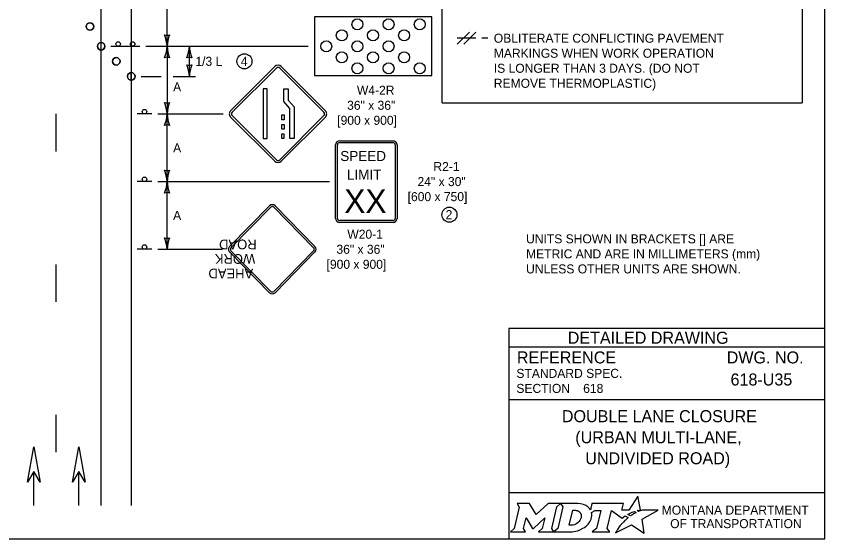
# Model space of a CAD drawing. Extents: x 49991.4 to 50021, y 49987.6 to 50011.4.
# Drawn here: x 50003.24 to 50008.61, y 50000.06 to 50003.54 of the extents above; entities that cross this region are included whole.
import ezdxf

# ---------------------------------------------------------------- set-up
doc = ezdxf.new("R2010")
doc.units = 0
for name, color, linetype in [('Level 1', 7, 'Continuous'), ('Level 2', 7, 'Continuous'), ('Level 3', 7, 'Continuous')]:
    doc.layers.add(name, color=color, linetype=linetype)

msp = doc.modelspace()

# ---------------------------------------------------------------- linework, layer by layer
at = {"layer": 'Level 1'}
for p, q in [((50004.006, 50011.0404), (50004.006, 50000.2848)), ((50003.806, 50000.2848), (50003.806, 50005.3678)), ((50006.1725, 50003.3523), (50006.2525, 50003.4323)), ((50006.2149, 50003.3523), (50006.2949, 50003.4323)), ((50006.2949, 50003.3923), (50006.1725, 50003.3923)), ((50003.8709, 50003.3385), (50003.9669, 50003.3385)), ((50003.9669, 50003.3385), (50004.0629, 50003.3385)), ((50004.6659, 50002.9095), (50004.9599, 50003.2036)), ((50004.9698, 50003.1936), (50004.6758, 50002.8996)), ((50004.9698, 50003.1936), (50004.9698, 50003.1936)), ((50005.286, 50002.8996), (50004.992, 50003.1936)), ((50005.0019, 50003.2036), (50005.2959, 50002.9095)), ((50004.9098, 50003.056), (50004.8823, 50003.056)), ((50004.8823, 50003.056), (50004.8823, 50002.7244)), ((50004.9098, 50002.7244), (50004.9098, 50003.056)), ((50005.0206, 50002.9703), (50005.0206, 50003.056)), ((50005.0206, 50003.056), (50005.0481, 50003.056)), ((50005.0481, 50003.056), (50005.0481, 50002.9805)), ((50005.0599, 50002.9246), (50005.0206, 50002.9703)), ((50005.0481, 50002.9805), (50005.0874, 50002.9348)), ((50003.5061, 50002.6382), (50003.5061, 50002.8882)), ((50004.142, 50002.8885), (50004.046, 50002.8885)), ((50005.0599, 50002.7244), (50005.0599, 50002.9246)), ((50005.0874, 50002.9348), (50005.0874, 50002.7244)), ((50004.9599, 50002.5735), (50004.6659, 50002.8675)), ((50004.6758, 50002.8774), (50004.9698, 50002.5834)), ((50004.992, 50002.5834), (50005.286, 50002.8774)), ((50005.2959, 50002.8675), (50005.0019, 50002.5735)), ((50005.0062, 50002.8504), (50005.0062, 50002.8818)), ((50005.0062, 50002.8818), (50005.0208, 50002.8818)), ((50005.0208, 50002.8504), (50005.0062, 50002.8504)), ((50005.0208, 50002.8818), (50005.0208, 50002.8504)), ((50005.0062, 50002.7874), (50005.0062, 50002.8188)), ((50005.0062, 50002.8188), (50005.0208, 50002.8188)), ((50005.0208, 50002.7874), (50005.0062, 50002.7874)), ((50005.0208, 50002.8188), (50005.0208, 50002.7874)), ((50005.0058, 50002.7244), (50005.0058, 50002.7559)), ((50005.0058, 50002.7559), (50005.0204, 50002.7559)), ((50005.0204, 50002.7559), (50005.0204, 50002.7244)), ((50004.8823, 50002.7244), (50004.9098, 50002.7244)), ((50005.0204, 50002.7244), (50005.0058, 50002.7244)), ((50005.0874, 50002.7244), (50005.0599, 50002.7244)), ((50005.3636, 50002.1938), (50005.3636, 50002.6833)), ((50005.376, 50002.1938), (50005.376, 50002.6833)), ((50005.3908, 50002.7105), (50005.7453, 50002.7105)), ((50005.3908, 50002.6981), (50005.7453, 50002.6981)), ((50005.76, 50002.6833), (50005.76, 50002.1938)), ((50005.7724, 50002.6833), (50005.7724, 50002.1938)), ((50004.142, 50002.4385), (50004.046, 50002.4385)), ((50004.6596, 50002.0066), (50004.9248, 50002.2773)), ((50004.6685, 50001.998), (50004.9337, 50002.2686)), ((50004.9523, 50002.2686), (50005.2174, 50001.998)), ((50004.9611, 50002.2773), (50005.2263, 50002.0066)), ((50005.7453, 50002.179), (50005.3908, 50002.179)), ((50005.7453, 50002.1666), (50005.3908, 50002.1666)), ((50004.142, 50001.9885), (50004.046, 50001.9885)), ((50004.9337, 50001.7084), (50004.6685, 50001.9791)), ((50005.2174, 50001.9791), (50004.9523, 50001.7084)), ((50004.9248, 50001.6997), (50004.6596, 50001.9704)), ((50005.2263, 50001.9704), (50004.9611, 50001.6997)), ((50003.5061, 50001.6382), (50003.5061, 50001.8882)), ((50003.5061, 50000.6382), (50003.5061, 50000.8882)), ((50003.3576, 50000.2848), (50003.3576, 50000.5107)), ((50003.3578, 50000.2848), (50003.3578, 50000.5107)), ((50003.6568, 50000.2848), (50003.6568, 50000.5107)), ((50003.657, 50000.2848), (50003.657, 50000.5107))]:
    msp.add_line(p, q, dxfattribs=at)
for points in [[(50008.6146, 50011.2628), (50000.3356, 50011.2628), (50000.3356, 50000.0624), (50008.6146, 50000.0624)], [(50005.2224, 50003.1435), (50006.0021, 50003.1435), (50006.0021, 50003.5335), (50005.2224, 50003.5335)], [(50005.2224, 50003.1435), (50006.0021, 50003.1435), (50006.0021, 50003.5335), (50005.2224, 50003.5335)], [(50003.3158, 50000.4384), (50003.3576, 50000.6749), (50003.3994, 50000.4384), (50003.3576, 50000.5106)], [(50003.615, 50000.4384), (50003.6568, 50000.6749), (50003.6986, 50000.4384), (50003.6568, 50000.5106)]]:
    msp.add_lwpolyline(points, close=True, dxfattribs=at)
for points in [[(50004.006, 50003.1635), (50004.006, 50003.1135)], [(50004.006, 50003.1135), (50004.006, 50003.1635)], [(50004.9279, 50002.7037), (50004.9281, 50002.7039)]]:
    msp.add_lwpolyline(points, dxfattribs=at)
for centre, radius in [((50003.731, 50003.47), 0.025), ((50005.5086, 50003.4845), 0.0366), ((50005.5086, 50003.4845), 0.0366), ((50005.7157, 50003.4845), 0.0366), ((50005.7157, 50003.4845), 0.0366), ((50005.9228, 50003.4845), 0.0366), ((50005.9228, 50003.4845), 0.0366), ((50005.405, 50003.4114), 0.0366), ((50005.405, 50003.4114), 0.0366), ((50005.6121, 50003.4114), 0.0366), ((50005.6121, 50003.4114), 0.0366), ((50005.8192, 50003.4114), 0.0366), ((50005.8192, 50003.4114), 0.0366), ((50005.3014, 50003.3383), 0.0366), ((50005.3014, 50003.3383), 0.0366), ((50005.5086, 50003.3383), 0.0366), ((50005.5086, 50003.3383), 0.0366), ((50005.7157, 50003.3383), 0.0366), ((50005.7157, 50003.3383), 0.0366), ((50003.806, 50003.3385), 0.025), ((50003.9189, 50003.3537), 0.0152), ((50004.0149, 50003.3537), 0.0152), ((50005.405, 50003.2652), 0.0366), ((50005.405, 50003.2652), 0.0366), ((50005.6121, 50003.2652), 0.0366), ((50005.6121, 50003.2652), 0.0366), ((50005.8192, 50003.2652), 0.0366), ((50005.8192, 50003.2652), 0.0366), ((50003.906, 50003.2385), 0.025), ((50005.5086, 50003.1921), 0.0366), ((50005.5086, 50003.1921), 0.0366), ((50005.7157, 50003.1921), 0.0366), ((50005.7157, 50003.1921), 0.0366), ((50005.9228, 50003.1921), 0.0366), ((50005.9228, 50003.1921), 0.0366), ((50004.0059, 50003.1385), 0.025), ((50004.0939, 50002.9037), 0.0152), ((50004.0939, 50002.4537), 0.0152), ((50004.0939, 50002.0037), 0.0152)]:
    msp.add_circle(centre, radius, dxfattribs=at)
for centre, radius, start, end in [((50003.731, 50003.47), 0.025, 0, 180), ((50003.731, 50003.47), 0.025, 180, 0), ((50003.806, 50003.3385), 0.025, 0, 180), ((50003.806, 50003.3385), 0.025, 180, 0), ((50003.906, 50003.2385), 0.025, 0, 180), ((50003.906, 50003.2385), 0.025, 180, 0), ((50004.9809, 50003.1826), 0.0297, 45.0001, 134.9999), ((50004.0059, 50003.1385), 0.025, 89.6871, 180), ((50004.0059, 50003.1385), 0.025, 0, 89.6871), ((50004.9809, 50003.1826), 0.0157, 45.0001, 134.9999), ((50004.0059, 50003.1385), 0.025, 180, 270.3129), ((50004.0059, 50003.1385), 0.025, 270.3129, 0), ((50004.6869, 50002.8885), 0.0297, 134.9999, 225.0001), ((50004.6869, 50002.8885), 0.0157, 134.9999, 225.0001), ((50005.2749, 50002.8885), 0.0157, 314.9999, 45.0001), ((50005.2749, 50002.8885), 0.0297, 314.9999, 45.0001), ((50005.3908, 50002.6833), 0.0272, 90, 180), ((50005.3908, 50002.6833), 0.0148, 90, 180), ((50005.7453, 50002.6833), 0.0272, 0, 90), ((50005.7453, 50002.6833), 0.0148, 0, 90), ((50004.9809, 50002.5945), 0.0297, 225.0001, 314.9999), ((50004.9809, 50002.5945), 0.0157, 225.0001, 314.9999), ((50005.3908, 50002.1938), 0.0272, 180, 270), ((50005.3908, 50002.1938), 0.0148, 180, 270), ((50005.7453, 50002.1938), 0.0148, 270, 360), ((50005.7453, 50002.1938), 0.0272, 270, 360)]:
    msp.add_arc(centre, radius, start, end, dxfattribs=at)
for centre, major_axis, ratio, start_param, end_param in [((50004.943, 50002.2591), (0, 0.0258), 0.98963, 5.497787, 7.068583), ((50004.943, 50002.2591), (0, 0.0134), 0.98, 5.497787, 7.068583), ((50004.6777, 50001.9885), (0, 0.0258), 0.98963, 0.785394, 2.356194), ((50004.6777, 50001.9885), (0, 0.0134), 0.98, 0.785394, 2.356194), ((50005.2082, 50001.9885), (0, 0.0134), 0.98, 3.926991, 5.497787), ((50005.2083, 50001.9884), (0, 0.0258), 0.98963, 3.926991, 5.497787), ((50004.943, 50001.7178), (0, -0.0134), 0.98, 5.497795, 7.068583), ((50004.943, 50001.7178), (0, -0.0258), 0.98963, 5.497795, 7.068583)]:
    msp.add_ellipse(centre, major_axis=major_axis, ratio=ratio, start_param=start_param, end_param=end_param, dxfattribs=at)
at = {"layer": 'Level 2'}
for p, q in [((50006.0725, 50002.9623), (50006.0725, 50004.7223)), ((50008.4639, 50004.7223), (50008.4639, 50002.9623)), ((50006.3749, 50003.3923), (50006.3349, 50003.3923)), ((50006.0725, 50002.9623), (50008.4639, 50002.9623)), ((50008.6146, 50001.4624), (50006.5146, 50001.4624)), ((50006.5146, 50001.4624), (50006.5146, 50000.0624)), ((50008.6146, 50001.3374), (50006.5146, 50001.3374)), ((50008.2507, 50001.1223), (50008.2507, 50001.1223)), ((50007.0089, 50001.0629), (50007.0089, 50001.0629)), ((50008.6146, 50000.9874), (50006.5146, 50000.9874)), ((50007.5646, 50000.7383), (50007.5646, 50000.7383)), ((50008.6146, 50000.3693), (50006.5146, 50000.3693))]:
    msp.add_line(p, q, dxfattribs=at)
for points in [[(50007.3771, 50000.2447), (50007.3668, 50000.2503), (50007.3784, 50000.2531), (50007.39, 50000.2551), (50007.3726, 50000.3452), (50007.3131, 50000.2539), (50007.2658, 50000.2532), (50007.2761, 50000.2973), (50007.0669, 50000.2974), (50007.0568, 50000.2549), (50007.051, 50000.2632)], [(50006.5701, 50000.2974), (50006.5842, 50000.274), (50006.5507, 50000.1307), (50006.525, 50000.1082), (50006.6266, 50000.1082), (50006.6131, 50000.131), (50006.6293, 50000.2011), (50006.673, 50000.1321), (50006.6783, 50000.1321), (50006.7534, 50000.2016), (50006.737, 50000.1305), (50006.7123, 50000.1085), (50006.8139, 50000.1085), (50006.8001, 50000.1318), (50006.8333, 50000.2742)], [(50006.8333, 50000.2742), (50006.8586, 50000.2974), (50006.7762, 50000.2974), (50006.6966, 50000.2244), (50006.6521, 50000.2971), (50006.5701, 50000.2974)], [(50006.9722, 50000.2974), (50006.8586, 50000.2974), (50006.8733, 50000.2745), (50006.8394, 50000.1307), (50006.8139, 50000.1085), (50006.9245, 50000.1085)], [(50006.9962, 50000.2107), (50006.995, 50000.2026), (50006.9918, 50000.1933), (50006.9876, 50000.1851), (50006.982, 50000.1776), (50006.9755, 50000.1707), (50006.9676, 50000.1644), (50006.9593, 50000.1597), (50006.9502, 50000.1558), (50006.9411, 50000.1535), (50006.9319, 50000.1526), (50006.916, 50000.1526), (50006.9396, 50000.2526), (50006.9556, 50000.2526), (50006.9632, 50000.252), (50006.9708, 50000.2501), (50006.9774, 50000.2471), (50006.9835, 50000.2429), (50006.9883, 50000.2379), (50006.992, 50000.2319), (50006.9947, 50000.2257), (50006.9963, 50000.2183), (50006.9963, 50000.2153), (50006.9962, 50000.2107)], [(50007.0636, 50000.2383), (50007.0882, 50000.2514), (50007.1251, 50000.2514), (50007.0965, 50000.1309), (50007.069, 50000.1082), (50007.1852, 50000.1082), (50007.1682, 50000.1311), (50007.1964, 50000.2513), (50007.2677, 50000.1996), (50007.2888, 50000.2147), (50007.3085, 50000.2038)], [(50007.2527, 50000.1479), (50007.2374, 50000.1235), (50007.2327, 50000.116), (50007.2269, 50000.1074), (50007.2246, 50000.1031), (50007.3299, 50000.1562), (50007.4138, 50000.1011), (50007.4007, 50000.1938), (50007.5076, 50000.2522), (50007.4583, 50000.253), (50007.4282, 50000.2534), (50007.4074, 50000.2537), (50007.4006, 50000.2522), (50007.3957, 50000.251), (50007.3873, 50000.2487), (50007.3771, 50000.2447)], [(50007.3267, 50000.2171), (50007.3243, 50000.2154), (50007.306, 50000.225), (50007.3163, 50000.2307), (50007.3204, 50000.2329), (50007.329, 50000.2369), (50007.3347, 50000.2395), (50007.3426, 50000.2425), (50007.3499, 50000.2452), (50007.3617, 50000.2378), (50007.3577, 50000.2357), (50007.3531, 50000.2332), (50007.3489, 50000.231), (50007.3439, 50000.2281), (50007.342, 50000.227), (50007.3393, 50000.2254), (50007.3368, 50000.224), (50007.3345, 50000.2224), (50007.3319, 50000.2206), (50007.3292, 50000.2188), (50007.3267, 50000.2171)], [(50007.2666, 50000.164), (50007.2666, 50000.164)], [(50006.9702, 50000.1158), (50006.9786, 50000.1184), (50006.9916, 50000.1238), (50007.012, 50000.1348)]]:
    msp.add_lwpolyline(points, dxfattribs=at)
for centre in [(50004.7579, 50003.2385), (50006.1199, 50002.2185)]:
    msp.add_circle(centre, 0.0501, dxfattribs=at)
for centre, radius, start, end in [((50006.9953, 50000.219), 0.0709, 339.5329, 15.8582), ((50006.9513, 50000.2363), 0.1183, 300.9103, 339.1383)]:
    msp.add_arc(centre, radius, start, end, dxfattribs=at)
for centre, major_axis, ratio, start_param, end_param in [((50006.9701, 50000.25), (0.0834, -0.0037), 0.568097, 0.61298, 1.570796), ((50007.0257, 50000.2573), (0.0361, -0.0295), 0.469099, 1.225588, 1.570796), ((50007.2974, 50000.1941), (-0.0112, -0.0097), 0.021651, 3.157348, 6.283185), ((50007.2597, 50000.1559), (-0.00694, -0.00806), 0.008222, 0, 3.137361), ((50007.2764, 50000.1742), (-0.0098, -0.0102), 0.016458, 3.141593, 6.279097), ((50006.9248, 50000.2568), (0, 0.1484), 0.987302, 3.139398, 3.456847)]:
    msp.add_ellipse(centre, major_axis=major_axis, ratio=ratio, start_param=start_param, end_param=end_param, dxfattribs=at)
at = {"layer": 'Level 3'}
for p, q in [((50004.244, 50003.3385), (50004.244, 50003.8602)), ((50004.1029, 50003.3385), (50005.1824, 50003.3385)), ((50004.244, 50003.3385), (50004.244, 50002.8885)), ((50004.392, 50003.1385), (50004.392, 50003.3385)), ((50004.0708, 50003.1385), (50004.204, 50003.1385)), ((50004.284, 50003.1385), (50004.432, 50003.1385)), ((50004.182, 50002.8885), (50004.6172, 50002.8885)), ((50004.244, 50002.4385), (50004.244, 50002.8885)), ((50004.182, 50002.4385), (50005.3236, 50002.4385)), ((50004.244, 50001.9886), (50004.244, 50002.4385)), ((50004.182, 50001.9885), (50004.6122, 50001.9885))]:
    msp.add_line(p, q, dxfattribs=at)
for centre, radius, start, end in [((50004.244, 50003.4667), 0.0548, 252.1388, 287.8612), ((50004.0113, 50003.327), 0.233, 2.8273, 22.0772), ((50004.4661, 50003.3294), 0.2223, 157.456, 177.6395), ((50004.0219, 50003.3477), 0.2223, 337.456, 357.6395), ((50004.4767, 50003.35), 0.233, 182.8273, 202.0772), ((50004.1699, 50003.3477), 0.2223, 337.456, 357.6395), ((50004.6247, 50003.35), 0.233, 182.8273, 202.0772), ((50004.244, 50003.2103), 0.0548, 72.1388, 107.8612), ((50004.392, 50003.2103), 0.0548, 72.1388, 107.8612), ((50004.392, 50003.2667), 0.0548, 252.1388, 287.8612), ((50004.1593, 50003.127), 0.233, 2.8273, 22.0772), ((50004.6141, 50003.1294), 0.2223, 157.456, 177.6395), ((50004.244, 50003.0167), 0.0548, 252.1388, 287.8612), ((50004.0113, 50002.877), 0.233, 2.8273, 22.0772), ((50004.4661, 50002.8794), 0.2223, 157.456, 177.6395), ((50004.0219, 50002.8977), 0.2223, 337.456, 357.6395), ((50004.4767, 50002.9), 0.233, 182.8273, 202.0772), ((50004.244, 50002.7603), 0.0548, 72.1388, 107.8612), ((50004.244, 50002.5667), 0.0548, 252.1388, 287.8612), ((50004.0113, 50002.427), 0.233, 2.8273, 22.0772), ((50004.4661, 50002.4294), 0.2223, 157.456, 177.6395), ((50004.0219, 50002.4477), 0.2223, 337.456, 357.6395), ((50004.4767, 50002.45), 0.233, 182.8273, 202.0772), ((50004.244, 50002.3103), 0.0548, 72.1388, 107.8612), ((50004.244, 50002.1167), 0.0548, 252.1388, 287.8612), ((50004.0113, 50001.977), 0.233, 2.8273, 22.0772), ((50004.4661, 50001.9794), 0.2223, 157.456, 177.6395)]:
    msp.add_arc(centre, radius, start, end, dxfattribs=at)

# ---------------------------------------------------------------- texts
at = {"layer": 'Level 1'}
for s, height, p in [('SPEED', 0.06696, (50005.3949, 50002.5753)), ('LIMIT', 0.06696, (50005.4392, 50002.4515)), ('XX', 0.15775, (50005.4209, 50002.2295))]:
    msp.add_text(s, height=height, dxfattribs=at).set_placement(p)
for s, p in [('ROAD', (50004.8388, 50002.053)), ('WORK', (50004.8297, 50001.9563)), ('AHEAD', (50004.816, 50001.8595))]:
    msp.add_text(s, height=0.06453, rotation=180, dxfattribs=at).set_placement(p)
at = {"layer": 'Level 2'}
for s, height, p in [('OBLITERATE CONFLICTING PAVEMENT', 0.06, (50006.4149, 50003.3623)), ('MARKINGS WHEN WORK OPERATION', 0.06, (50006.4149, 50003.2623)), ('1/3 L', 0.06, (50004.432, 50003.2085)), ('4', 0.06, (50004.734, 50003.2085)), ('IS LONGER THAN 3 DAYS. (DO NOT ', 0.06, (50006.4149, 50003.1623)), ('REMOVE THERMOPLASTIC)', 0.06, (50006.4149, 50003.0623)), ('W4-2R', 0.06, (50005.5052, 50003.0162)), ('36" x 36"', 0.06, (50005.4401, 50002.9162)), ('[900 x 900]', 0.06, (50005.3745, 50002.8162)), ('R2-1', 0.06, (50006.0134, 50002.5085)), ('24" x 30"', 0.06, (50005.9079, 50002.4085)), ('[600 x 750]', 0.06, (50005.8423, 50002.3085)), ('2', 0.06, (50006.0948, 50002.1885)), ('W20-1', 0.06, (50005.4415, 50002.0584)), ('UNITS SHOWN IN BRACKETS [] ARE ', 0.06, (50006.6294, 50002.0278)), ('36" x 36"', 0.06, (50005.3692, 50001.9584)), ('METRIC AND ARE IN MILLIMETERS (mm) ', 0.06, (50006.6294, 50001.9278)), ('[900 x 900]', 0.06, (50005.3036, 50001.8584)), ('UNLESS OTHER UNITS ARE SHOWN.', 0.06, (50006.6294, 50001.8278)), ('DETAILED DRAWING', 0.0799, (50006.9063, 50001.3599)), ('REFERENCE', 0.08, (50006.5682, 50001.229)), ('DWG. NO.', 0.08, (50007.9624, 50001.229)), ('STANDARD SPEC.', 0.06, (50006.5649, 50001.133)), ('618-U35', 0.08, (50007.988, 50001.0823)), ('SECTION', 0.06, (50006.5649, 50001.033)), ('618', 0.06, (50007.0089, 50001.0329)), ('DOUBLE LANE CLOSURE', 0.08, (50006.8672, 50000.8383)), ('(URBAN MULTI-LANE,', 0.08, (50006.9564, 50000.6983)), (' UNDIVIDED ROAD)', 0.08, (50006.993, 50000.5583)), ('MONTANA DEPARTMENT', 0.06, (50007.5308, 50000.2236)), ('OF TRANSPORTATION', 0.06, (50007.587, 50000.1336))]:
    msp.add_text(s, height=height, dxfattribs=at).set_placement(p)
for p in [(50004.284, 50003.0385), (50004.284, 50002.6335), (50004.284, 50002.1835)]:
    msp.add_text('A', height=0.06, rotation=360, dxfattribs=at).set_placement(p)

doc.saveas('drawing.dxf')
